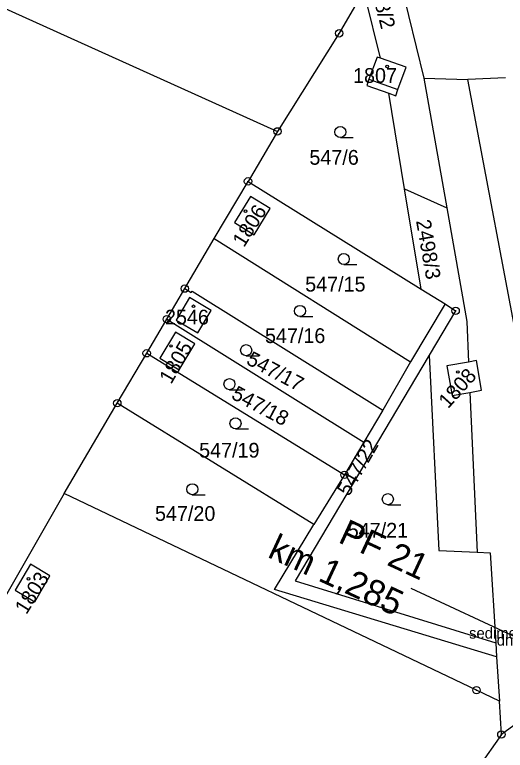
# Model space of a CAD drawing. Extents: x -555757 to -553364, y -1100723 to -1096439.
# Drawn here: x -553937 to -553870.5, y -1099734.7 to -1099635 of the extents above; entities that cross this region are included whole.
import ezdxf

# ---------------------------------------------------------------- set-up
doc = ezdxf.new("R2010")
doc.units = 0
for name, color, linetype in [('00_NÁVRH - Řezy', 7, 'Continuous'), ('BUDOVY', 7, 'Continuous'), ('C$SLO$PARCELY', 7, 'Continuous'), ('HRANICE$PARCELY', 7, 'Continuous'), ('POPIS', 7, 'Continuous'), ('SLOUPY', 7, 'Continuous'), ('SLUCKOV$$C$RA', 7, 'Continuous'), ('VSTUP', 7, 'Continuous'), ('ZNA$KY$KULTUR', 7, 'Continuous')]:
    doc.layers.add(name, color=color, linetype=linetype)

# ---------------------------------------------------------------- blocks, each defined once
blk = doc.blocks.new('4$02')
at = {"layer": 'SLOUPY'}
blk.add_circle((0, 0), 0.175, dxfattribs=at)
blk = doc.blocks.new('3$04')
at = {"layer": 'ZNA$KY$KULTUR'}
blk.add_line((0.007, 0), (1.757, 0), dxfattribs=at)
blk.add_circle((0.007, 0.75), 0.75, dxfattribs=at)
blk = doc.blocks.new('1$05')
at = {"layer": 'SLOUPY'}
for radius in [0.5, 0.032]:
    blk.add_circle((0, 0), radius, dxfattribs=at)

msp = doc.modelspace()

# ---------------------------------------------------------------- linework, layer by layer
at = {"layer": '00_NÁVRH - Řezy'}
msp.add_line((-553850.279, -1099728.082), (-553883.248, -1099712.755), dxfattribs=at)
at = {"layer": 'HRANICE$PARCELY'}
for p, q in [((-553887.39, -1099640.92), (-553889.65, -1099631.73)), ((-553884.14, -1099658.6), (-553886.29, -1099645.66)), ((-553901.36, -1099650.82), (-553905.35, -1099657.59)), ((-553909.92, -1099665.34), (-553905.35, -1099657.59)), ((-553905.35, -1099657.59), (-553881.88, -1099672.18)), ((-553881.88, -1099672.18), (-553884.14, -1099658.6)), ((-553884.14, -1099658.6), (-553878.43, -1099661.18)), ((-553913.92, -1099672.12), (-553909.92, -1099665.34)), ((-553909.92, -1099665.34), (-553883.33, -1099682.03)), ((-553916.35, -1099676.25), (-553913.92, -1099672.12)), ((-553881.88, -1099672.18), (-553878.64, -1099674.19)), ((-553878.64, -1099674.19), (-553883.33, -1099682.03)), ((-553878.64, -1099674.19), (-553877.22, -1099675.13)), ((-553877.22, -1099675.13), (-553880.8, -1099681.15)), ((-553919.08, -1099680.88), (-553916.35, -1099676.25)), ((-553916.35, -1099676.25), (-553889.67, -1099692.9)), ((-553923.06, -1099687.63), (-553919.08, -1099680.88)), ((-553919.08, -1099680.88), (-553892.27, -1099697.34)), ((-553883.33, -1099682.03), (-553887.06, -1099688.57)), ((-553875.28, -1099686.17), (-553874.3, -1099707.83)), ((-553930.27, -1099699.87), (-553923.06, -1099687.63)), ((-553896.45, -1099704.09), (-553923.06, -1099687.63)), ((-553887.06, -1099688.57), (-553889.67, -1099692.9)), ((-553889.67, -1099692.9), (-553892.27, -1099697.34)), ((-553892.27, -1099697.34), (-553896.45, -1099704.09)), ((-553930.27, -1099699.87), (-553955.86, -1099744.63)), ((-553874.39, -1099726.51), (-553930.27, -1099699.87)), ((-553901.75, -1099712.86), (-553896.45, -1099704.09)), ((-553871.66, -1099721.98), (-553901.75, -1099712.86)), ((-553871.77, -1099720.09), (-553871.66, -1099721.98)), ((-553871.66, -1099721.98), (-553871.29, -1099727.98)), ((-553871.29, -1099727.98), (-553874.39, -1099726.51)), ((-553871.02, -1099732.51), (-553871.29, -1099727.98))]:
    msp.add_line(p, q, dxfattribs=at)
for points in [[(-554113.42, -1099555.01), (-553992.5, -1099609.65), (-553901.36, -1099650.82)], [(-553884.63, -1099630.82), (-553881.53, -1099643.61), (-553878.43, -1099661.18)], [(-553889.65, -1099631.73), (-553893, -1099637.54), (-553901.36, -1099650.82)], [(-553819.96, -1099633.32), (-553820.36, -1099635.42), (-553827.65, -1099682.1), (-553830.01, -1099691.17), (-553848.53, -1099708.98), (-553857.54, -1099719.82), (-553860.57, -1099723.47), (-553863.68, -1099727.2), (-553871.02, -1099732.51)], [(-553887.39, -1099640.92), (-553887.86, -1099640.76), (-553888.96, -1099643.77), (-553889.27, -1099644.62), (-553886.29, -1099645.66)], [(-553886.29, -1099645.66), (-553885.34, -1099646), (-553885.03, -1099645.15), (-553883.93, -1099642.14), (-553887.39, -1099640.92)], [(-553907.19, -1099663.18), (-553904.53, -1099664.83), (-553902.37, -1099661.25), (-553904.99, -1099659.65), (-553907.19, -1099663.18)], [(-553878.43, -1099661.18), (-553875.72, -1099676.58), (-553875.47, -1099682.06)], [(-553913.92, -1099672.12), (-553913.04, -1099672.64), (-553912.92, -1099672.45), (-553887.06, -1099688.57)], [(-553915.1, -1099676.38), (-553912.17, -1099678.13), (-553910.36, -1099675.07), (-553913.28, -1099673.33), (-553915.1, -1099676.38)], [(-553917.29, -1099681.54), (-553914.69, -1099683.11), (-553912.56, -1099679.6), (-553915.16, -1099678.03), (-553917.29, -1099681.54)], [(-553880.8, -1099681.15), (-553898.94, -1099711.68), (-553871.77, -1099720.09)], [(-553880.8, -1099681.15), (-553879.48, -1099707.6), (-553874.3, -1099707.83)], [(-553875.47, -1099682.06), (-553878.39, -1099682.59), (-553877.68, -1099686.61), (-553875.28, -1099686.17)], [(-553875.28, -1099686.17), (-553873.7, -1099685.89), (-553874.41, -1099681.87), (-553875.47, -1099682.06)], [(-553874.3, -1099707.83), (-553872.52, -1099707.91), (-553871.77, -1099720.09)], [(-553934.83, -1099709.46), (-553936.89, -1099712.95), (-553934.25, -1099714.53), (-553932.19, -1099711.04), (-553934.83, -1099709.46)], [(-553871.02, -1099732.51), (-553874.13, -1099736.94), (-553893.58, -1099759.08)]]:
    msp.add_lwpolyline(points, dxfattribs=at)
at = {"layer": 'SLUCKOV$$C$RA'}
for p, q in [((-553888.96, -1099643.77), (-553885.03, -1099645.15)), ((-553881.53, -1099643.61), (-553875.56, -1099643.8)), ((-553870.46, -1099643.58), (-553875.56, -1099643.8)), ((-553860.57, -1099723.47), (-553875.56, -1099643.8))]:
    msp.add_line(p, q, dxfattribs=at)

# ---------------------------------------------------------------- block references
at = {"layer": 'BUDOVY'}
for p in [(-553886.49, -1099642.04), (-553905.68, -1099661.62), (-553912.73, -1099674.51), (-553915.78, -1099679.89), (-553876.91, -1099683.41), (-553935.1, -1099711.44)]:
    msp.add_blockref('4$02', p, dxfattribs=at)
at = {"layer": 'VSTUP'}
for p in [(-553893, -1099637.54), (-553901.36, -1099650.82), (-553905.35, -1099657.59), (-553913.92, -1099672.12), (-553877.22, -1099675.13), (-553916.35, -1099676.25), (-553919.08, -1099680.88), (-553923.06, -1099687.63), (-553892.27, -1099697.34), (-553874.39, -1099726.51), (-553871.02, -1099732.51)]:
    msp.add_blockref('1$05', p, dxfattribs=at)
at = {"layer": 'ZNA$KY$KULTUR'}
for p in [(-553892.84, -1099651.66), (-553892.38, -1099668.86), (-553898.32, -1099675.89), (-553905.61, -1099681.21), (-553907.87, -1099685.81), (-553907.05, -1099691.12), (-553912.91, -1099700.04), (-553886.41, -1099701.39)]:
    msp.add_blockref('3$04', p, dxfattribs=at)

# ---------------------------------------------------------------- texts
at = {"layer": '00_NÁVRH - Řezy'}
for s, p in [('PF 21', (-553893.283, -1099706.421)), ('km 1,285', (-553902.838, -1099708.427))]:
    msp.add_text(s, height=3.5, rotation=335.06717, dxfattribs=at).set_placement(p)
at = {"layer": 'C$SLO$PARCELY'}
for s, rotation, p in [('2498/2', 284, (-553889.265, -1099629.161)), ('1806', 58, (-553905.891, -1099666.626)), ('2498/3', 280, (-553882.596, -1099662.945)), ('1805', 60, (-553915.769, -1099685.168)), ('547/17', 332, (-553905.715, -1099682.265)), ('1808', 48, (-553878.243, -1099688.468)), ('547/18', 332, (-553907.749, -1099686.946)), ('547/22', 60, (-553891.682, -1099700.367)), ('1803', 58, (-553935.378, -1099716.363))]:
    msp.add_text(s, height=2, rotation=rotation, dxfattribs=at).set_placement(p)
for s, p in [('1807', (-553891.117, -1099644.25)), ('547/6', (-553897.033, -1099655.34)), ('547/15', (-553897.605, -1099672.52)), ('2546', (-553916.602, -1099676.979)), ('547/16', (-553903.054, -1099679.49)), ('547/19', (-553911.974, -1099695.01)), ('547/20', (-553917.955, -1099703.58)), ('547/21', (-553891.838, -1099705.85))]:
    msp.add_text(s, height=2, dxfattribs=at).set_placement(p)
at = {"layer": 'POPIS'}
for s, p in [('sediment 238.07', (-553875.396, -1099719.525)), ('dno 237.12', (-553871.646, -1099720.475))]:
    msp.add_text(s, height=1.5, dxfattribs=at).set_placement(p)

doc.saveas('drawing.dxf')
